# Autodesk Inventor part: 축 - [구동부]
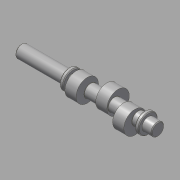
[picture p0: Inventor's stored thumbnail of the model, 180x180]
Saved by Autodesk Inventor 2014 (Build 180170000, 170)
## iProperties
Company: 한국ATC센터
Created: 2014-08
Part Number: 축 - [구동부]
Document SubType Name: Modeling
Designer: KYOUNG IL JANG
Density: 7.86 g/cm^3
Material: 강철, 연강
Appearance: 강철
Mass: 516.584 g
Surface Area: 162.515 cm^2
Volume: 65.7231 cm^3
Author: KYOUNG IL JANG
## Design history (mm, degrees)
sketch "스케치1"
  geometry: L1 (-91.5, 0)-(91.5, 0); L2 (-91.5, 0)-(-91.5, 8.5); L3 (-91.5, 8.5)-(-27.5, 8.5); L4 (-27.5, 8.5)-(-27.5, 13); L5 (-27.5, 13)-(-22.5, 13); L6 (-22.5, 13)-(-22.5, 8.5); L7 (-22.5, 8.5)-(73.5, 8.5); L8 (73.5, 8.5)-(73.5, 13); L9 (73.5, 13)-(78.5, 13); L10 (78.5, 13)-(78.5, 8.5); L11 (78.5, 8.5)-(91.5, 8.5); L12 (91.5, 8.5)-(91.5, 0); 2 further points
  constraints: 24 end point, 5 parallel, 1 coincident, 1 horizontal, 1 midpoint, 1 perpendicular
  dimensions: "d0" = 183 distance of L1.start L1.end (derived); "d2" = 17 diameter of L3 L1; "d3" = 26 diameter of L5 L1; "d4" = 17 diameter of L7 L1; "d5" = 26 diameter of L9 L1; "d6" = 17 diameter of L11 L1; "d7" = 5 distance of L8.end L9.end; "d8" = 5 distance of L4.end L5.end; "d10" = 64 distance of L2.end L3.end; "d11" = 13 distance of L10.end L11.end; "d35" = 96 distance between parallel lines of L8 L6
revolve "회전1" sketch "스케치1" stored, may be unused: angle "d12" = 90 deg
node "작업 평면7"
sketch "스케치6"
  geometry: C1 r 15 at (0, 5); 1 further point
  constraints: 1 centre point, 1 vertical alignment
  dimensions: "d37" = 30 diameter of C1; "d38" = 5 distance of C1.centre point (0, 0)
extrude "돌출4" join sketch "스케치6" stored distance "d33" = 15; taper "d34" = 0 deg
node "작업 평면8"
sketch "스케치7"
  geometry: L1 (0, 0)-(-6.5, -11.258); L2 (0, 0)-(13, 0); C1 r 15 at (-2.5, -4.33); A1 r 13 centre (0, 0) between (-6.5, -11.258) and (13, 0) reference; 1 further point
  constraints: 4 end point, 2 point on circle, 1 centre point, 1 horizontal, 1 point on line
  dimensions: "d40" = 120 deg angle of L1 L2; "d41" = 30 diameter of C1; "d42" = 5 distance of point (0, 0) C1.centre
extrude "돌출5" join sketch "스케치7" stored distance "d43" = 15; taper "d44" = 0 deg
node "작업 평면9"
sketch "스케치8"
  geometry: L1 (0, 0)-(4.25, -7.361); L2 (0, 0)-(-8.5, 0); C1 r 15 at (2.5, -4.33); A1 r 8.5 centre (0, 0) between (4.25, -7.361) and (-8.5, 0) reference; 1 further point
  constraints: 4 end point, 2 point on circle, 1 centre point, 1 horizontal, 1 point on line
  dimensions: "d46" = 120 deg angle of L1 L2; "d47" = 30 diameter of C1; "d48" = 5 distance of point (0, 0) C1.centre
extrude "돌출6" join sketch "스케치8" stored distance "d49" = 15; taper "d50" = 0 deg
node "작업 평면3"
sketch "스케치5"
  geometry: L1 (32, 8.5)-(32, -8.5) reference; L2 (27.5, -2.5)-(14.5, -2.5); L3 (14.5, 2.5)-(27.5, 2.5); A1 r 2.5 centre (14.5, 0) between (14.5, 2.5) and (14.5, -2.5); A2 r 2.5 centre (27.5, 0) between (27.5, -2.5) and (27.5, 2.5); 4 further points
  constraints: 4 end point, 4 point on circle, 4 tangent, 2 centre point, 2 point on line, 1 horizontal alignment, 1 midpoint, 1 parallel, 1 perpendicular
  dimensions: "d23" = 5 distance between parallel lines of L3 L2; "d36" = 20 dimension on A1 L1; "d52" = 2 distance edge to line of A2 L1
extrude "돌출3" cut sketch "스케치5" distance "d25" = 3; taper "d26" = 0 deg
chamfer "모따기1" distance "d27" = 1; stored, may be unused: second distance "d28" = 2, angle "d29" = 45 deg
fillet "모깎기1" dims "d51" = 0.3
chamfer "모따기2" distance "d53" = 1; stored, may be unused: second distance "d54" = 2, angle "d55" = 45 deg
node "작업 평면10"
node "솔리드1"
other parameters: "d39" = -32, "d45" = 32
